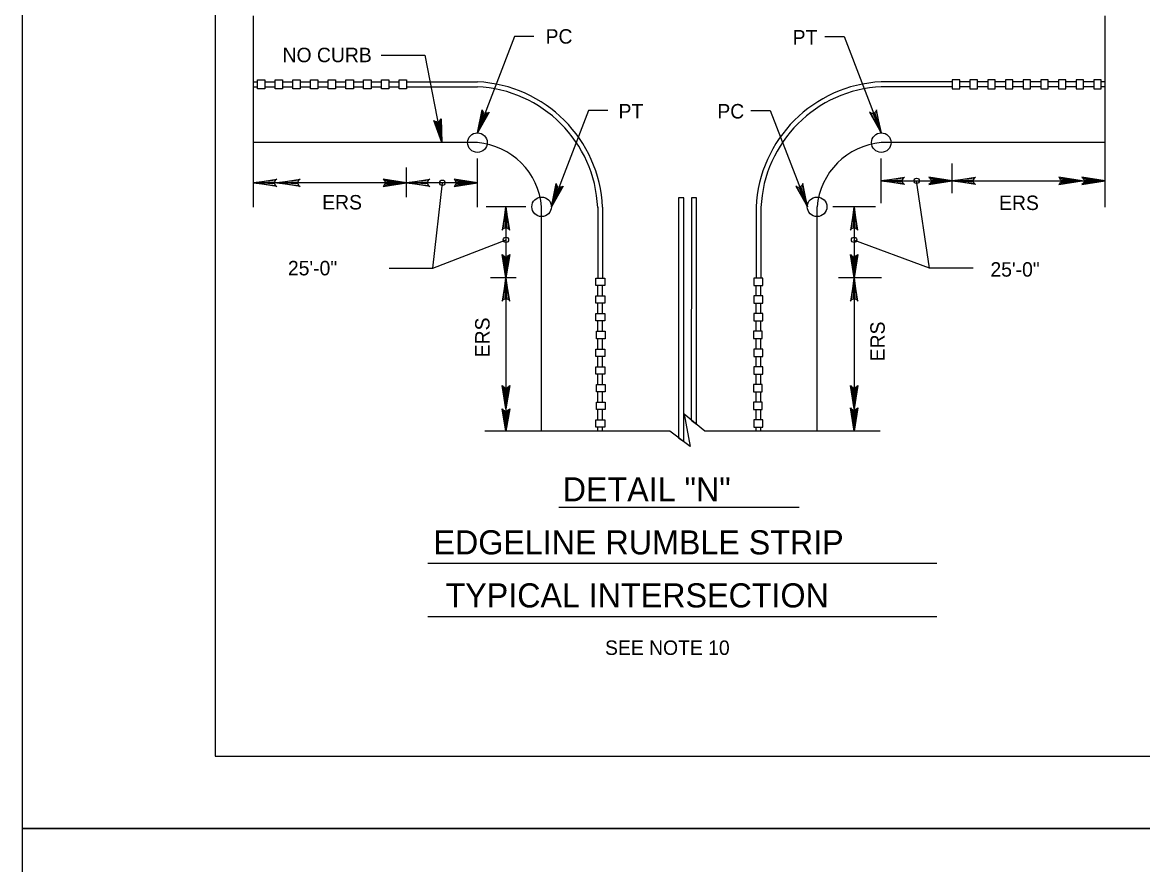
# Model space of a CAD drawing. Extents: x 632008 to 634206, y 294231 to 297795.
# Drawn here: x 632007.9 to 632240.2, y 296005.1 to 296179.8 of the extents above; entities that cross this region are included whole.
import ezdxf

# ---------------------------------------------------------------- set-up
doc = ezdxf.new("R2010")
doc.units = 0
for name, color, linetype in [('1', 7, 'Continuous'), ('Level 2', 7, 'Continuous'), ('PLT-BNDY', 7, 'Continuous')]:
    doc.layers.add(name, color=color, linetype=linetype)

msp = doc.modelspace()

# ---------------------------------------------------------------- linework, layer by layer
at = {"layer": '1'}
for p, q in [((632119.12, 296079.29), (632168.99, 296079.29)), ((632091.93, 296067.61), (632197.52, 296067.61)), ((632091.93, 296056.61), (632197.52, 296056.61))]:
    msp.add_line(p, q, dxfattribs=at)
msp.add_lwpolyline([(632833.86, 296027.62), (632833.86, 296591.62), (632047.86, 296591.62), (632047.86, 296027.62), (632833.86, 296027.62), (632833.86, 296053.98), (632633.86, 296053.98), (632633.86, 296118.66), (632833.86, 296118.66), (632833.86, 296147.62), (632633.86, 296147.62), (632633.86, 296027.62), (632712.66, 296027.62), (632712.66, 296053.98), (632712.66, 296027.62), (632789.66, 296027.62), (632789.66, 296053.98), (632789.66, 296041.66), (632833.86, 296041.66)], dxfattribs=at)
for points in [[(632145.04, 296092.85), (632145.04, 296143.41), (632143.99, 296143.41), (632143.99, 296093.64)], [(632147.68, 296096.46), (632147.68, 296143.41), (632146.63, 296143.41), (632146.62, 296097.29)]]:
    msp.add_lwpolyline(points, close=True, dxfattribs=at)
at = {"layer": 'Level 2'}
for p, q in [((632055.77, 296141.49), (632055.77, 296181.16)), ((632232.49, 296141.49), (632232.49, 296181.16)), ((632055.79, 296167.48), (632056.61, 296167.48)), ((632055.79, 296166.47), (632056.61, 296166.47)), ((632058.14, 296167.48), (632060.29, 296167.48)), ((632058.14, 296166.47), (632060.29, 296166.47)), ((632061.82, 296167.48), (632063.96, 296167.48)), ((632061.82, 296166.47), (632063.96, 296166.47)), ((632065.49, 296167.48), (632067.63, 296167.48)), ((632065.49, 296166.47), (632067.63, 296166.47)), ((632069.16, 296167.48), (632071.3, 296167.48)), ((632069.16, 296166.47), (632071.3, 296166.47)), ((632072.83, 296167.48), (632074.98, 296167.48)), ((632072.83, 296166.47), (632074.98, 296166.47)), ((632076.51, 296167.48), (632078.65, 296167.48)), ((632076.51, 296166.47), (632078.65, 296166.47)), ((632080.18, 296167.48), (632082.32, 296167.48)), ((632080.18, 296166.47), (632082.32, 296166.47)), ((632083.85, 296167.48), (632085.99, 296167.48)), ((632083.85, 296166.47), (632085.99, 296166.47)), ((632087.52, 296167.48), (632102.25, 296167.48)), ((632087.52, 296166.47), (632102.25, 296166.47)), ((632200.76, 296167.48), (632186.03, 296167.48)), ((632200.76, 296166.47), (632186.03, 296166.47)), ((632204.43, 296167.48), (632202.29, 296167.48)), ((632204.43, 296166.47), (632202.29, 296166.47)), ((632208.1, 296167.48), (632205.96, 296167.48)), ((632208.1, 296166.47), (632205.96, 296166.47)), ((632211.77, 296167.48), (632209.63, 296167.48)), ((632211.77, 296166.47), (632209.63, 296166.47)), ((632215.45, 296167.48), (632213.3, 296167.48)), ((632215.45, 296166.47), (632213.3, 296166.47)), ((632219.12, 296167.48), (632216.98, 296167.48)), ((632219.12, 296166.47), (632216.98, 296166.47)), ((632222.79, 296167.48), (632220.65, 296167.48)), ((632222.79, 296166.47), (632220.65, 296166.47)), ((632226.46, 296167.48), (632224.32, 296167.48)), ((632226.46, 296166.47), (632224.32, 296166.47)), ((632230.14, 296167.48), (632227.99, 296167.48)), ((632230.14, 296166.47), (632227.99, 296166.47)), ((632232.49, 296167.48), (632231.67, 296167.48)), ((632232.49, 296166.47), (632231.67, 296166.47)), ((632102.25, 296154.87), (632055.77, 296154.87)), ((632232.49, 296154.87), (632186.03, 296154.87)), ((632087.53, 296143.54), (632087.53, 296149.71)), ((632102.25, 296141.49), (632102.25, 296151.58)), ((632186.03, 296142.31), (632186.03, 296151.58)), ((632200.75, 296144.36), (632200.75, 296150.53)), ((632102.25, 296146.54), (632055.79, 296146.54)), ((632092.98, 296128.84), (632094.98, 296146.53)), ((632186.03, 296146.95), (632232.49, 296146.95)), ((632196.02, 296128.84), (632193.36, 296146.94)), ((632112.29, 296141.56), (632104.03, 296141.56)), ((632108.16, 296141.56), (632108.16, 296095.01)), ((632115.57, 296095.01), (632115.57, 296141.56)), ((632127.22, 296141.47), (632127.22, 296126.75)), ((632128.23, 296141.47), (632128.23, 296126.75)), ((632160.05, 296141.47), (632160.05, 296126.75)), ((632161.06, 296141.47), (632161.06, 296126.75)), ((632172.71, 296095.02), (632172.71, 296141.56)), ((632184.8, 296141.56), (632175.97, 296141.56)), ((632180.39, 296141.56), (632180.39, 296095.02)), ((632110.31, 296126.83), (632104.98, 296126.83)), ((632186.1, 296126.83), (632177.16, 296126.83)), ((632127.22, 296123.08), (632127.22, 296125.22)), ((632128.23, 296123.08), (632128.23, 296125.22)), ((632160.05, 296123.08), (632160.05, 296125.22)), ((632161.06, 296123.08), (632161.06, 296125.22)), ((632127.22, 296119.41), (632127.22, 296121.55)), ((632128.23, 296119.41), (632128.23, 296121.55)), ((632160.05, 296119.41), (632160.05, 296121.55)), ((632161.06, 296119.41), (632161.06, 296121.55)), ((632127.22, 296115.73), (632127.22, 296117.88)), ((632128.23, 296115.73), (632128.23, 296117.88)), ((632160.05, 296115.74), (632160.05, 296117.88)), ((632161.06, 296115.74), (632161.06, 296117.88)), ((632127.22, 296112.06), (632127.22, 296114.2)), ((632128.23, 296112.06), (632128.23, 296114.2)), ((632160.05, 296112.06), (632160.05, 296114.21)), ((632161.06, 296112.06), (632161.06, 296114.21)), ((632127.22, 296108.39), (632127.22, 296110.53)), ((632128.23, 296108.39), (632128.23, 296110.53)), ((632160.05, 296108.39), (632160.05, 296110.53)), ((632161.06, 296108.39), (632161.06, 296110.53)), ((632127.22, 296104.72), (632127.22, 296106.86)), ((632128.23, 296104.72), (632128.23, 296106.86)), ((632160.05, 296104.72), (632160.05, 296106.86)), ((632161.06, 296104.72), (632161.06, 296106.86)), ((632127.22, 296101.04), (632127.22, 296103.19)), ((632128.23, 296101.04), (632128.23, 296103.19)), ((632160.05, 296101.05), (632160.05, 296103.19)), ((632161.06, 296101.05), (632161.06, 296103.19)), ((632127.22, 296097.37), (632127.22, 296099.51)), ((632128.23, 296097.37), (632128.23, 296099.51)), ((632149.44, 296095.02), (632145.12, 296098.52)), ((632145.12, 296098.52), (632146.41, 296091.83)), ((632160.05, 296097.37), (632160.05, 296099.51)), ((632161.06, 296097.37), (632161.06, 296099.51)), ((632142.16, 296095.02), (632103.81, 296095.01)), ((632127.22, 296095.01), (632127.22, 296095.84)), ((632128.23, 296095.01), (632128.23, 296095.84)), ((632146.41, 296091.83), (632142.16, 296095.02)), ((632185.8, 296095.02), (632149.44, 296095.02)), ((632160.05, 296095.02), (632160.05, 296095.84)), ((632161.06, 296095.02), (632161.06, 296095.84))]:
    msp.add_line(p, q, dxfattribs=at)
for points in [[(632113.98, 296176.87), (632109.92, 296176.87), (632102.25, 296156.9)], [(632174.3, 296176.87), (632178.35, 296176.87), (632186.03, 296156.9)], [(632082.29, 296173.01), (632091.33, 296173.01), (632094.88, 296154.87)], [(632104.4, 296161.01), (632104.03, 296160.97), (632102.25, 296156.9), (632104.4, 296161.01), (632104.67, 296161.16), (632102.25, 296156.9), (632103.59, 296161.12), (632103.34, 296161.39), (632102.25, 296156.9), (632103.22, 296161.7), (632103.34, 296161.39)], [(632129.32, 296161.53), (632125.27, 296161.53), (632117.59, 296141.56)], [(632158.96, 296161.53), (632163.01, 296161.53), (632170.69, 296141.56)], [(632183.88, 296161.01), (632184.25, 296160.97), (632186.03, 296156.9), (632183.88, 296161.01), (632183.61, 296161.16), (632186.03, 296156.9), (632184.69, 296161.12), (632184.94, 296161.39), (632186.03, 296156.9), (632185.06, 296161.7), (632184.94, 296161.39)], [(632094.55, 296159.5), (632094.25, 296159.27), (632094.88, 296154.87), (632094.55, 296159.5), (632094.7, 296159.77), (632094.88, 296154.87), (632093.8, 296159.17), (632093.45, 296159.26), (632094.88, 296154.87), (632093.18, 296159.46), (632093.45, 296159.26)], [(632060.39, 296145.96), (632060.22, 296146.29), (632055.79, 296146.54), (632060.39, 296145.96), (632060.63, 296145.76), (632055.79, 296146.54), (632060.22, 296146.76), (632060.38, 296147.08), (632055.79, 296146.54), (632060.63, 296147.31), (632060.38, 296147.08)], [(632065.21, 296145.96), (632065.04, 296146.29), (632060.61, 296146.54), (632065.21, 296145.96), (632065.45, 296145.76), (632060.61, 296146.54), (632065.04, 296146.76), (632065.2, 296147.08), (632060.61, 296146.54), (632065.45, 296147.31), (632065.2, 296147.08)], [(632082.92, 296145.96), (632083.09, 296146.29), (632087.53, 296146.54), (632082.92, 296145.96), (632082.69, 296145.76), (632087.53, 296146.54), (632083.1, 296146.76), (632082.94, 296147.08), (632087.53, 296146.54), (632082.69, 296147.31), (632082.94, 296147.08)], [(632092.13, 296145.96), (632091.96, 296146.29), (632087.53, 296146.54), (632092.13, 296145.96), (632092.36, 296145.76), (632087.53, 296146.54), (632091.95, 296146.76), (632092.12, 296147.08), (632087.53, 296146.54), (632092.36, 296147.31), (632092.12, 296147.08)], [(632097.65, 296145.96), (632097.82, 296146.29), (632102.25, 296146.54), (632097.65, 296145.96), (632097.41, 296145.76), (632102.25, 296146.54), (632097.82, 296146.76), (632097.66, 296147.08), (632102.25, 296146.54), (632097.41, 296147.31), (632097.66, 296147.08)], [(632190.63, 296146.37), (632190.46, 296146.7), (632186.03, 296146.95), (632190.63, 296146.37), (632190.87, 296146.17), (632186.03, 296146.95), (632190.46, 296147.17), (632190.62, 296147.49), (632186.03, 296146.95), (632190.87, 296147.72), (632190.62, 296147.49)], [(632196.15, 296146.37), (632196.32, 296146.7), (632200.75, 296146.95), (632196.15, 296146.37), (632195.91, 296146.17), (632200.75, 296146.95), (632196.33, 296147.17), (632196.16, 296147.49), (632200.75, 296146.95), (632195.91, 296147.72), (632196.16, 296147.49)], [(632205.36, 296146.37), (632205.19, 296146.7), (632200.75, 296146.95), (632205.36, 296146.37), (632205.59, 296146.17), (632200.75, 296146.95), (632205.18, 296147.17), (632205.34, 296147.49), (632200.75, 296146.95), (632205.59, 296147.72), (632205.34, 296147.49)], [(632223.07, 296146.37), (632223.24, 296146.7), (632227.67, 296146.95), (632223.07, 296146.37), (632222.83, 296146.17), (632227.67, 296146.95), (632223.24, 296147.17), (632223.08, 296147.49), (632227.67, 296146.95), (632222.83, 296147.72), (632223.08, 296147.49)], [(632227.89, 296146.37), (632228.06, 296146.7), (632232.49, 296146.95), (632227.89, 296146.37), (632227.65, 296146.17), (632232.49, 296146.95), (632228.06, 296147.17), (632227.9, 296147.49), (632232.49, 296146.95), (632227.65, 296147.72), (632227.9, 296147.49)], [(632119.74, 296145.67), (632119.37, 296145.63), (632117.59, 296141.56), (632119.74, 296145.67), (632120.01, 296145.82), (632117.59, 296141.56), (632118.93, 296145.78), (632118.68, 296146.05), (632117.59, 296141.56), (632118.56, 296146.36), (632118.68, 296146.05)], [(632168.54, 296145.67), (632168.91, 296145.63), (632170.69, 296141.56), (632168.54, 296145.67), (632168.27, 296145.82), (632170.69, 296141.56), (632169.35, 296145.78), (632169.6, 296146.05), (632170.69, 296141.56), (632169.72, 296146.36), (632169.6, 296146.05)], [(632108.74, 296136.95), (632108.4, 296137.12), (632108.16, 296141.56), (632108.74, 296136.95), (632108.94, 296136.72), (632108.16, 296141.56), (632107.94, 296137.13), (632107.61, 296136.97), (632108.16, 296141.56), (632107.39, 296136.72), (632107.61, 296136.97)], [(632180.97, 296136.95), (632180.63, 296137.12), (632180.39, 296141.56), (632180.97, 296136.95), (632181.17, 296136.72), (632180.39, 296141.56), (632180.17, 296137.13), (632179.84, 296136.97), (632180.39, 296141.56), (632179.62, 296136.72), (632179.84, 296136.97)], [(632083.94, 296128.84), (632092.98, 296128.84), (632108.18, 296134.69)], [(632205.06, 296128.84), (632196.02, 296128.84), (632180.35, 296134.65)], [(632108.74, 296131.43), (632108.4, 296131.26), (632108.16, 296126.83), (632108.74, 296131.43), (632108.94, 296131.67), (632108.16, 296126.83), (632107.94, 296131.26), (632107.61, 296131.42), (632108.16, 296126.83), (632107.39, 296131.67), (632107.61, 296131.42)], [(632180.97, 296131.43), (632180.63, 296131.26), (632180.39, 296126.83), (632180.97, 296131.43), (632181.17, 296131.67), (632180.39, 296126.83), (632180.17, 296131.26), (632179.84, 296131.42), (632180.39, 296126.83), (632179.62, 296131.67), (632179.84, 296131.42)], [(632108.74, 296122.23), (632108.4, 296122.4), (632108.16, 296126.83), (632108.74, 296122.23), (632108.94, 296121.99), (632108.16, 296126.83), (632107.94, 296122.4), (632107.61, 296122.24), (632108.16, 296126.83), (632107.39, 296121.99), (632107.61, 296122.24)], [(632180.97, 296122.23), (632180.63, 296122.4), (632180.39, 296126.83), (632180.97, 296122.23), (632181.17, 296121.99), (632180.39, 296126.83), (632180.17, 296122.4), (632179.84, 296122.24), (632180.39, 296126.83), (632179.62, 296121.99), (632179.84, 296122.24)], [(632108.74, 296104.23), (632108.41, 296104.07), (632108.16, 296099.63), (632108.74, 296104.23), (632108.94, 296104.47), (632108.16, 296099.63), (632107.94, 296104.06), (632107.62, 296104.22), (632108.16, 296099.63), (632107.39, 296104.47), (632107.62, 296104.22)], [(632180.97, 296104.23), (632180.64, 296104.07), (632180.39, 296099.63), (632180.97, 296104.23), (632181.17, 296104.47), (632180.39, 296099.63), (632180.17, 296104.06), (632179.85, 296104.22), (632180.39, 296099.63), (632179.62, 296104.47), (632179.85, 296104.22)], [(632108.74, 296099.42), (632108.41, 296099.26), (632108.16, 296095.01), (632108.74, 296099.42), (632108.94, 296099.65), (632108.16, 296095.01), (632107.94, 296099.26), (632107.62, 296099.41), (632108.16, 296095.01), (632107.39, 296099.65), (632107.62, 296099.41)], [(632180.97, 296099.62), (632180.64, 296099.45), (632180.39, 296095.02), (632180.97, 296099.62), (632181.17, 296099.85), (632180.39, 296095.02), (632180.17, 296099.44), (632179.85, 296099.61), (632180.39, 296095.02), (632179.62, 296099.85), (632179.85, 296099.61)]]:
    msp.add_lwpolyline(points, dxfattribs=at)
for points in [[(632058.14, 296166.06), (632056.61, 296166.06), (632056.61, 296167.9), (632058.14, 296167.9)], [(632061.82, 296166.06), (632060.29, 296166.06), (632060.29, 296167.9), (632061.82, 296167.9)], [(632065.49, 296166.06), (632063.96, 296166.06), (632063.96, 296167.9), (632065.49, 296167.9)], [(632069.16, 296166.06), (632067.63, 296166.06), (632067.63, 296167.9), (632069.16, 296167.9)], [(632072.83, 296166.06), (632071.3, 296166.06), (632071.3, 296167.9), (632072.83, 296167.9)], [(632076.51, 296166.06), (632074.98, 296166.06), (632074.98, 296167.9), (632076.51, 296167.9)], [(632080.18, 296166.06), (632078.65, 296166.06), (632078.65, 296167.9), (632080.18, 296167.9)], [(632083.85, 296166.06), (632082.32, 296166.06), (632082.32, 296167.9), (632083.85, 296167.9)], [(632087.52, 296166.06), (632085.99, 296166.06), (632085.99, 296167.9), (632087.52, 296167.9)], [(632200.76, 296166.06), (632202.29, 296166.06), (632202.29, 296167.9), (632200.76, 296167.9)], [(632204.43, 296166.06), (632205.96, 296166.06), (632205.96, 296167.9), (632204.43, 296167.9)], [(632208.1, 296166.06), (632209.63, 296166.06), (632209.63, 296167.9), (632208.1, 296167.9)], [(632211.77, 296166.06), (632213.3, 296166.06), (632213.3, 296167.9), (632211.77, 296167.9)], [(632215.45, 296166.06), (632216.98, 296166.06), (632216.98, 296167.9), (632215.45, 296167.9)], [(632219.12, 296166.06), (632220.65, 296166.06), (632220.65, 296167.9), (632219.12, 296167.9)], [(632222.79, 296166.06), (632224.32, 296166.06), (632224.32, 296167.9), (632222.79, 296167.9)], [(632226.46, 296166.06), (632227.99, 296166.06), (632227.99, 296167.9), (632226.46, 296167.9)], [(632230.14, 296166.06), (632231.67, 296166.06), (632231.67, 296167.9), (632230.14, 296167.9)], [(632128.68, 296126.75), (632128.68, 296125.22), (632126.84, 296125.22), (632126.84, 296126.75)], [(632159.6, 296126.75), (632159.6, 296125.22), (632161.44, 296125.22), (632161.44, 296126.75)], [(632128.68, 296123.08), (632128.68, 296121.55), (632126.84, 296121.55), (632126.84, 296123.08)], [(632159.6, 296123.08), (632159.6, 296121.55), (632161.44, 296121.55), (632161.44, 296123.08)], [(632128.68, 296119.41), (632128.68, 296117.88), (632126.84, 296117.88), (632126.84, 296119.41)], [(632159.6, 296119.41), (632159.6, 296117.88), (632161.44, 296117.88), (632161.44, 296119.41)], [(632128.77, 296115.73), (632128.77, 296114.2), (632126.93, 296114.2), (632126.93, 296115.73)], [(632159.51, 296115.74), (632159.51, 296114.21), (632161.35, 296114.21), (632161.35, 296115.74)], [(632128.68, 296112.06), (632128.68, 296110.53), (632126.84, 296110.53), (632126.84, 296112.06)], [(632159.6, 296112.06), (632159.6, 296110.53), (632161.44, 296110.53), (632161.44, 296112.06)], [(632128.68, 296108.39), (632128.68, 296106.86), (632126.84, 296106.86), (632126.84, 296108.39)], [(632159.6, 296108.39), (632159.6, 296106.86), (632161.44, 296106.86), (632161.44, 296108.39)], [(632128.77, 296104.72), (632128.77, 296103.19), (632126.93, 296103.19), (632126.93, 296104.72)], [(632159.51, 296104.72), (632159.51, 296103.19), (632161.35, 296103.19), (632161.35, 296104.72)], [(632128.77, 296101.04), (632128.77, 296099.51), (632126.93, 296099.51), (632126.93, 296101.04)], [(632159.51, 296101.05), (632159.51, 296099.51), (632161.35, 296099.51), (632161.35, 296101.05)], [(632128.68, 296097.37), (632128.68, 296095.84), (632126.84, 296095.84), (632126.84, 296097.37)], [(632159.6, 296097.37), (632159.6, 296095.84), (632161.44, 296095.84), (632161.44, 296097.37)]]:
    msp.add_lwpolyline(points, close=True, dxfattribs=at)
for centre, radius in [((632102.25, 296154.87), 2.03), ((632186.03, 296154.87), 2.03), ((632193.36, 296146.94), 0.558), ((632094.98, 296146.54), 0.558), ((632115.57, 296141.56), 2.03), ((632172.71, 296141.56), 2.03), ((632108.17, 296134.71), 0.558), ((632180.38, 296134.71), 0.558)]:
    msp.add_circle(centre, radius, dxfattribs=at)
for centre, radius, start, end in [((632100.95, 296140.21), 26.29, 2.6354, 87.2786), ((632100.95, 296140.21), 27.3, 2.6354, 87.2786), ((632187.33, 296140.21), 27.3, 92.7214, 177.3646), ((632187.33, 296140.21), 26.29, 92.7214, 177.3646), ((632101.02, 296140.32), 14.6, 4.837, 85.163), ((632187.26, 296140.32), 14.6, 94.837, 175.163)]:
    msp.add_arc(centre, radius, start, end, dxfattribs=at)
at = {"layer": 'PLT-BNDY'}
for points in [[(632007.86, 296606.62), (632848.86, 296606.62), (632848.86, 296012.62), (632007.86, 296012.62)], [(632007.86, 296012.62), (632848.86, 296012.62), (632848.86, 295418.62), (632007.86, 295418.62)]]:
    msp.add_lwpolyline(points, close=True, dxfattribs=at)

# ---------------------------------------------------------------- texts
at = {"layer": 'Level 2'}
for s, height, p in [('PC', 3, (632116.39, 296175.4)), ('PT', 3, (632167.64, 296175.21)), ('NO CURB', 3, (632061.83, 296171.55)), ('PT', 3, (632131.53, 296159.88)), ('PC', 3, (632152.02, 296159.88)), ('ERS', 3, (632070.05, 296141)), ('ERS', 3, (632210.47, 296140.89)), ('25\'-0"', 3, (632062.94, 296127.34)), ('25\'-0"', 3, (632208.67, 296127.07)), ('DETAIL "N"', 5, (632119.95, 296080.46)), ('EDGELINE RUMBLE STRIP', 5, (632093.14, 296069.46)), ('TYPICAL INTERSECTION', 5, (632095.64, 296058.46)), ('SEE NOTE 10', 3, (632128.72, 296048.61))]:
    msp.add_text(s, height=height, dxfattribs=at).set_placement(p)
for p in [(632104.78, 296110.35), (632186.75, 296109.51)]:
    msp.add_text('ERS', height=3, rotation=90, dxfattribs=at).set_placement(p)

doc.saveas('drawing.dxf')
